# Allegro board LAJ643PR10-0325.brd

Outline 313.6 x 137.82 mm; copper layers: TOP, GND1, IN1, VCC, IN2, IN3, GND2, BOTTOM. Coordinates in mm from the lower left corner of the outline.

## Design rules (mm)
net group CLK_CNV_PRX_DTX_: nets CLK_CNV_PRX_DTX_N CLK_CNV_PRX_DTX_P
net group CLK_CNV_PTX_DRX_: nets CLK_CNV_PTX_DRX_N CLK_CNV_PTX_DRX_P
net group CNV_PRX_DTX_0: nets CNV_PRX_DTX_N0 CNV_PRX_DTX_P0
net group CNV_PRX_DTX_1: nets CNV_PRX_DTX_N1 CNV_PRX_DTX_P1
net group CNV_PTX_DRX_0: nets CNV_PTX_DRX_N0 CNV_PTX_DRX_P0
net group CNV_PTX_DRX_1: nets CNV_PTX_DRX_N1 CNV_PTX_DRX_P1
net group DDR_ALERT: nets DDR_M0_ALERT# DDR_M1_ALERT#
net group DDR_M0_CLK0: nets DDR_M0_CLK0 DDR_M0_CLK#0
net group DDR_M0_CLK1: nets DDR_M0_CLK1 DDR_M0_CLK#1
net group DDR_M0_DQS0: nets DDR_M0_DQS0 DDR_M0_DQS#0
net group DDR_M0_DQS1: nets DDR_M0_DQS1 DDR_M0_DQS#1
net group DDR_M0_DQS2: nets DDR_M0_DQS2 DDR_M0_DQS#2
net group DDR_M0_DQS3: nets DDR_M0_DQS3 DDR_M0_DQS#3
net group DDR_M0_DQS4: nets DDR_M0_DQS4 DDR_M0_DQS#4
net group DDR_M0_DQS5: nets DDR_M0_DQS5 DDR_M0_DQS#5
net group DDR_M0_DQS6: nets DDR_M0_DQS6 DDR_M0_DQS#6
net group DDR_M0_DQS7: nets DDR_M0_DQS7 DDR_M0_DQS#7
net group DDR_M1_CLK0: nets DDR_M1_CLK0 DDR_M1_CLK#0
net group DDR_M1_CLK1: nets DDR_M1_CLK1 DDR_M1_CLK#1
net group DDR_M1_DQS0: nets DDR_M1_DQS0 DDR_M1_DQS#0
net group DDR_M1_DQS1: nets DDR_M1_DQS1 DDR_M1_DQS#1
net group DDR_M1_DQS2: nets DDR_M1_DQS2 DDR_M1_DQS#2
net group DDR_M1_DQS3: nets DDR_M1_DQS3 DDR_M1_DQS#3
net group DDR_M1_DQS4: nets DDR_M1_DQS4 DDR_M1_DQS#4
net group DDR_M1_DQS5: nets DDR_M1_DQS5 DDR_M1_DQS#5
net group DDR_M1_DQS6: nets DDR_M1_DQS6 DDR_M1_DQS#6
net group DDR_M1_DQS7: nets DDR_M1_DQS7 DDR_M1_DQS#7
net group DMI_CRX_PTX_0: nets DMI_CRX_PTX_N0 DMI_CRX_PTX_P0
net group DMI_CRX_PTX_1: nets DMI_CRX_PTX_N1 DMI_CRX_PTX_P1
net group DMI_CRX_PTX_2: nets DMI_CRX_PTX_N2 DMI_CRX_PTX_P2
net group DMI_CRX_PTX_3: nets DMI_CRX_PTX_N3 DMI_CRX_PTX_P3
net group DMI_CTX_PRX_0: nets DMI_CTX_PRX_N0 DMI_CTX_PRX_P0
net group DMI_CTX_PRX_1: nets DMI_CTX_PRX_N1 DMI_CTX_PRX_P1
net group DMI_CTX_PRX_2: nets DMI_CTX_PRX_N2 DMI_CTX_PRX_P2
net group DMI_CTX_PRX_3: nets DMI_CTX_PRX_N3 DMI_CTX_PRX_P3
net group EDP_AUX: nets EDP_AUXN EDP_AUXP
net group EDP_AUX_C: nets EDP_AUXN_C EDP_AUXP_C
net group EDP_TX0: nets EDP_TXN0 EDP_TXP0
net group EDP_TX0_C: nets EDP_TXN0_C EDP_TXP0_C
net group EDP_TX1: nets EDP_TXN1 EDP_TXP1
net group EDP_TX1_C: nets EDP_TXN1_C EDP_TXP1_C
net group EDP_TX2: nets EDP_TXN2 EDP_TXP2
net group EDP_TX2_C: nets EDP_TXN2_C EDP_TXP2_C
net group EDP_TX3: nets EDP_TXN3 EDP_TXP3
net group EDP_TX3_C: nets EDP_TXN3_C EDP_TXP3_C
net group FBA_CLKA0: nets FBA_CLKA0 FBA_CLKA0#
net group FBA_CLKA1: nets FBA_CLKA1 FBA_CLKA1#
net group FBA_WCK01: nets FBA_WCK01 FBA_WCK01#
net group FBA_WCK23: nets FBA_WCK23 FBA_WCK23#
net group FBA_WCK45: nets FBA_WCK45 FBA_WCK45#
net group FBA_WCK67: nets FBA_WCK67 FBA_WCK67#
net group FBB_CLKA0: nets FBB_CLKA0 FBB_CLKA0#
net group FBB_CLKA1: nets FBB_CLKA1 FBB_CLKA1#
net group FBB_WCK01: nets FBB_WCK01 FBB_WCK01#
net group FBB_WCK23: nets FBB_WCK23 FBB_WCK23#
net group FBB_WCK45: nets FBB_WCK45 FBB_WCK45#
net group FBB_WCK67: nets FBB_WCK67 FBB_WCK67#
net group GPU_DPE_0: nets GPU_DPE_N0 GPU_DPE_P0
net group GPU_DPE_0_C: nets GPU_DPE_N0_C GPU_DPE_P0_C
net group GPU_DPE_1: nets GPU_DPE_N1 GPU_DPE_P1
net group GPU_DPE_1_C: nets GPU_DPE_N1_C GPU_DPE_P1_C
net group GPU_DPE_2: nets GPU_DPE_N2 GPU_DPE_P2
net group GPU_DPE_2_C: nets GPU_DPE_N2_C GPU_DPE_P2_C
net group GPU_DPE_3: nets GPU_DPE_N3 GPU_DPE_P3
net group GPU_DPE_3_C: nets GPU_DPE_N3_C GPU_DPE_P3_C
net group GPU_DPE_AUX: nets GPU_DPE_AUXN GPU_DPE_AUXP
net group GPU_DPE_AUX_C: nets GPU_DPE_AUXN_C GPU_DPE_AUXP_C
net group GPU_HDMI_TX0: nets GPU_HDMI_TX0N GPU_HDMI_TX0P
net group GPU_HDMI_TX0_C: nets GPU_HDMI_TX0N_C GPU_HDMI_TX0P_C
net group GPU_HDMI_TX1: nets GPU_HDMI_TX1N GPU_HDMI_TX1P
net group GPU_HDMI_TX1_C: nets GPU_HDMI_TX1N_C GPU_HDMI_TX1P_C
net group GPU_HDMI_TX2: nets GPU_HDMI_TX2N GPU_HDMI_TX2P
net group GPU_HDMI_TX2_C: nets GPU_HDMI_TX2N_C GPU_HDMI_TX2P_C
net group GPU_HDMI_TXC: nets GPU_HDMI_TXCN GPU_HDMI_TXCP
net group GPU_HDMI_TXC_C: nets GPU_HDMI_TXCN_C GPU_HDMI_TXCP_C
net group LAN_MDI0: nets LAN_MDIN0 LAN_MDIP0
net group LAN_MDI1: nets LAN_MDIN1 LAN_MDIP1
net group LAN_MDI2: nets LAN_MDIN2 LAN_MDIP2
net group LAN_MDI3: nets LAN_MDIN3 LAN_MDIP3
net group LPC_CLK: nets CLK_PCI_LPC CLKOUT_LPC0
net group PCIE_PRX_DTX_9: nets PCIE_PRX_DTX_N9 PCIE_PRX_DTX_P9
net group PCIE_PRX_DTX_10: nets PCIE_PRX_DTX_N10 PCIE_PRX_DTX_P10
net group PCIE_PRX_DTX_11: nets PCIE_PRX_DTX_N11 PCIE_PRX_DTX_P11
net group PCIE_PRX_DTX_12: nets PCIE_PRX_DTX_N12 PCIE_PRX_DTX_P12
net group PCIE_PTX_C_DRX_9: nets PCIE_PTX_C_DRX_N9 PCIE_PTX_C_DRX_P9
net group PCIE_PTX_C_DRX_10: nets PCIE_PTX_C_DRX_N10 PCIE_PTX_C_DRX_P10
net group PCIE_PTX_C_DRX_11: nets PCIE_PTX_C_DRX_N11 PCIE_PTX_C_DRX_P11
net group PCIE_PTX_C_DRX_12: nets PCIE_PTX_C_DRX_N12 PCIE_PTX_C_DRX_P12
net group PCIE_PTX_DRX_9: nets PCIE_PTX_DRX_N9 PCIE_PTX_DRX_P9
net group PCIE_PTX_DRX_10: nets PCIE_PTX_DRX_N10 PCIE_PTX_DRX_P10
net group PCIE_PTX_DRX_11: nets PCIE_PTX_DRX_N11 PCIE_PTX_DRX_P11
net group PCIE_PTX_DRX_12: nets PCIE_PTX_DRX_N12 PCIE_PTX_DRX_P12
net group PCIE_RCOMP: nets PCIE_RCOMPN PCIE_RCOMPP
net group PEG_CRX_C_GTX_0: nets PEG_CRX_C_GTX_N0 PEG_CRX_C_GTX_P0
net group PEG_CRX_C_GTX_1: nets PEG_CRX_C_GTX_N1 PEG_CRX_C_GTX_P1
net group PEG_CRX_C_GTX_2: nets PEG_CRX_C_GTX_N2 PEG_CRX_C_GTX_P2
net group PEG_CRX_C_GTX_3: nets PEG_CRX_C_GTX_N3 PEG_CRX_C_GTX_P3
net group PEG_CRX_C_GTX_4: nets PEG_CRX_C_GTX_N4 PEG_CRX_C_GTX_P4
net group PEG_CRX_C_GTX_5: nets PEG_CRX_C_GTX_N5 PEG_CRX_C_GTX_P5
net group PEG_CRX_C_GTX_6: nets PEG_CRX_C_GTX_N6 PEG_CRX_C_GTX_P6
net group PEG_CRX_C_GTX_7: nets PEG_CRX_C_GTX_N7 PEG_CRX_C_GTX_P7
net group PEG_CRX_GTX_0: nets PEG_CRX_GTX_N0 PEG_CRX_GTX_P0
net group PEG_CRX_GTX_1: nets PEG_CRX_GTX_N1 PEG_CRX_GTX_P1
net group PEG_CRX_GTX_2: nets PEG_CRX_GTX_N2 PEG_CRX_GTX_P2
net group PEG_CRX_GTX_3: nets PEG_CRX_GTX_N3 PEG_CRX_GTX_P3
net group PEG_CRX_GTX_4: nets PEG_CRX_GTX_N4 PEG_CRX_GTX_P4
net group PEG_CRX_GTX_5: nets PEG_CRX_GTX_N5 PEG_CRX_GTX_P5
net group PEG_CRX_GTX_6: nets PEG_CRX_GTX_N6 PEG_CRX_GTX_P6
net group PEG_CRX_GTX_7: nets PEG_CRX_GTX_N7 PEG_CRX_GTX_P7
net group PEG_CTX_C_GRX_0: nets PEG_CTX_C_GRX_N0 PEG_CTX_C_GRX_P0
net group PEG_CTX_C_GRX_1: nets PEG_CTX_C_GRX_N1 PEG_CTX_C_GRX_P1
net group PEG_CTX_C_GRX_2: nets PEG_CTX_C_GRX_N2 PEG_CTX_C_GRX_P2
net group PEG_CTX_C_GRX_3: nets PEG_CTX_C_GRX_N3 PEG_CTX_C_GRX_P3
net group PEG_CTX_C_GRX_4: nets PEG_CTX_C_GRX_N4 PEG_CTX_C_GRX_P4
net group PEG_CTX_C_GRX_5: nets PEG_CTX_C_GRX_N5 PEG_CTX_C_GRX_P5
net group PEG_CTX_C_GRX_6: nets PEG_CTX_C_GRX_N6 PEG_CTX_C_GRX_P6
net group PEG_CTX_C_GRX_7: nets PEG_CTX_C_GRX_N7 PEG_CTX_C_GRX_P7
net group PEG_CTX_GRX_0: nets PEG_CTX_GRX_N0 PEG_CTX_GRX_P0
net group PEG_CTX_GRX_1: nets PEG_CTX_GRX_N1 PEG_CTX_GRX_P1
net group PEG_CTX_GRX_2: nets PEG_CTX_GRX_N2 PEG_CTX_GRX_P2
net group PEG_CTX_GRX_3: nets PEG_CTX_GRX_N3 PEG_CTX_GRX_P3
net group PEG_CTX_GRX_4: nets PEG_CTX_GRX_N4 PEG_CTX_GRX_P4
net group PEG_CTX_GRX_5: nets PEG_CTX_GRX_N5 PEG_CTX_GRX_P5
net group PEG_CTX_GRX_6: nets PEG_CTX_GRX_N6 PEG_CTX_GRX_P6
net group PEG_CTX_GRX_7: nets PEG_CTX_GRX_N7 PEG_CTX_GRX_P7
net group QPC: nets QPCN QPCP
net group RJ45_RX1: nets RJ45_RX1+ RJ45_RX1-
net group RJ45_TX0: nets RJ45_TX0+ RJ45_TX0-
net group RJ45_TX2: nets RJ45_TX2+ RJ45_TX2-
net group RJ45_TX3: nets RJ45_TX3+ RJ45_TX3-
net group SPK_L_CONN: nets SPK_L+_CONN SPK_L-_CONN
net group SPK_OUT_L: nets SPK_OUT_L+ SPK_OUT_L-
net group SPK_OUT_R: nets SPK_OUT_R+ SPK_OUT_R-
net group SPK_R_CONN: nets SPK_R+_CONN SPK_R-_CONN
net group SR_R: nets SRN_R SRP_R
net group TMDS_SNK_ML0_: nets TMDS_SNK_ML0_N TMDS_SNK_ML0_P
net group TMDS_SNK_ML0__R: nets TMDS_SNK_ML0_N_R TMDS_SNK_ML0_P_R
net group TMDS_SNK_ML1_: nets TMDS_SNK_ML1_N TMDS_SNK_ML1_P
net group TMDS_SNK_ML1__R: nets TMDS_SNK_ML1_N_R TMDS_SNK_ML1_P_R
net group TMDS_SNK_ML2_: nets TMDS_SNK_ML2_N TMDS_SNK_ML2_P
net group TMDS_SNK_ML2__R: nets TMDS_SNK_ML2_N_R TMDS_SNK_ML2_P_R
net group TMDS_SNK_ML3_: nets TMDS_SNK_ML3_N TMDS_SNK_ML3_P
net group TMDS_SNK_ML3__R: nets TMDS_SNK_ML3_N_R TMDS_SNK_ML3_P_R
net group U2D_D1: nets U2D_DN1 U2D_DP1
net group USB3_DPE_MRX_C_DTX_1: nets USB3_DPE_MRX_C_DTX_N1 USB3_DPE_MRX_C_DTX_P1
net group USB3_DPE_MRX_C_DTX_2: nets USB3_DPE_MRX_C_DTX_N2 USB3_DPE_MRX_C_DTX_P2
net group USB3_DPE_MRX_DTX_1: nets USB3_DPE_MRX_DTX_N1 USB3_DPE_MRX_DTX_P1
net group USB3_DPE_MRX_DTX_2: nets USB3_DPE_MRX_DTX_N2 USB3_DPE_MRX_DTX_P2
net group USB3_DPE_MTX_C_DRX_1: nets USB3_DPE_MTX_C_DRX_N1 USB3_DPE_MTX_C_DRX_P1
net group USB3_DPE_MTX_C_DRX_2: nets USB3_DPE_MTX_C_DRX_N2 USB3_DPE_MTX_C_DRX_P2
net group USB3_DPE_MTX_DRX_1: nets USB3_DPE_MTX_DRX_N1 USB3_DPE_MTX_DRX_P1
net group USB3_DPE_MTX_DRX_2: nets USB3_DPE_MTX_DRX_N2 USB3_DPE_MTX_DRX_P2
net group USB3_PRX_C_MTX_4: nets USB3_PRX_C_MTX_N4 USB3_PRX_C_MTX_P4
net group USB3_PRX_DTX_1: nets USB3_PRX_DTX_N1 USB3_PRX_DTX_P1
net group USB3_PRX_DTX_2: nets USB3_PRX_DTX_N2 USB3_PRX_DTX_P2
net group USB3_PRX_DTX_3: nets USB3_PRX_DTX_N3 USB3_PRX_DTX_P3
net group USB3_PRX_MTX_4: nets USB3_PRX_MTX_N4 USB3_PRX_MTX_P4
net group USB3_PRX_R_DTX_1: nets USB3_PRX_R_DTX_N1 USB3_PRX_R_DTX_P1
net group USB3_PTX_C_DRX_1: nets USB3_PTX_C_DRX_N1 USB3_PTX_C_DRX_P1
net group USB3_PTX_C_MRX_4: nets USB3_PTX_C_MRX_N4 USB3_PTX_C_MRX_P4
net group USB3_PTX_DRX_1: nets USB3_PTX_DRX_N1 USB3_PTX_DRX_P1
net group USB3_PTX_DRX_2: nets USB3_PTX_DRX_N2 USB3_PTX_DRX_P2
net group USB3_PTX_DRX_3: nets USB3_PTX_DRX_N3 USB3_PTX_DRX_P3
net group USB3_PTX_MRX_4: nets USB3_PTX_MRX_N4 USB3_PTX_MRX_P4
net group USB3_PTX_R_DRX_1: nets USB3_PTX_R_DRX_N1 USB3_PTX_R_DRX_P1
net group USB20_1: nets USB20_N1 USB20_P1
net group USB20_1_C: nets USB20_N1_C USB20_P1_C
net group USB20_2: nets USB20_N2 USB20_P2
net group USB20_3: nets USB20_N3 USB20_P3
net group USB20_4: nets USB20_N4 USB20_P4
net group USB20_4_L: nets USB20_N4_L USB20_P4_L
net group USB20_5: nets USB20_N5 USB20_P5
net group USB20_5_R: nets USB20_N5_R USB20_P5_R
net group USB20_6: nets USB20_N6 USB20_P6
net group USB20_9: nets USB20_N9 USB20_P9
net group USB20_14: nets USB20_N14 USB20_P14
net group W12: nets +PD_CC1 +PD_CC2
net group W15: nets DP_RCOMP PEG_RCOMP
net group COMBO JACK: nets +MIC2_VREFO HP_OUT_L HP_OUT_R HP_OUTL HP_OUTR HPOUT_L HPOUT_R INT_MIC INT_MIC_R
net group CPU_SIDEBAND: nets CPU_TRIGOUT CPU_TRIGOUT_R DDR_DRAMRST#_R DRAM_RESET# EC_PECI EC_VCCST_PG EC_VCCST_PG_R H_CPUPWRGD H_PECI H_PLTRST_CPU# H_PM_DOWN H_PM_DOWN_R H_PM_SYNC H_PM_SYNC_R H_PROCHOT# H_PROCHOT#_EC H_THERMTRIP# PCH_THERMTRIP# PCH_THERMTRIP#_R PCH_TRIGOUT PCH_TRIGOUT_R VR_HOT#
net group DDR_M0_CMD: nets DDR_M0_ACT# DDR_M0_BA0 DDR_M0_BA1 DDR_M0_BG0 DDR_M0_BG1 DDR_M0_MA0 DDR_M0_MA1 DDR_M0_MA2 DDR_M0_MA3 DDR_M0_MA4 DDR_M0_MA5 DDR_M0_MA6 DDR_M0_MA7 DDR_M0_MA8 DDR_M0_MA9 DDR_M0_MA10 DDR_M0_MA11 DDR_M0_MA12 DDR_M0_MA13 DDR_M0_MA14_WE# DDR_M0_MA15_CAS# DDR_M0_MA16_RAS# DDR_M0_PAR
net group DDR_M0_CTRL: nets DDR_M0_CKE0 DDR_M0_CKE1 DDR_M0_CS#0 DDR_M0_CS#1 DDR_M0_ODT0 DDR_M0_ODT1
net group DDR_M0_D0: nets DDR_M0_D0 DDR_M0_D1 DDR_M0_D2 DDR_M0_D3 DDR_M0_D4 DDR_M0_D5 DDR_M0_D6 DDR_M0_D7
net group DDR_M0_D1: nets DDR_M0_D8 DDR_M0_D9 DDR_M0_D10 DDR_M0_D11 DDR_M0_D12 DDR_M0_D13 DDR_M0_D14 DDR_M0_D15
net group DDR_M0_D2: nets DDR_M0_D16 DDR_M0_D17 DDR_M0_D18 DDR_M0_D19 DDR_M0_D20 DDR_M0_D21 DDR_M0_D22 DDR_M0_D23
net group DDR_M0_D3: nets DDR_M0_D24 DDR_M0_D25 DDR_M0_D26 DDR_M0_D27 DDR_M0_D28 DDR_M0_D29 DDR_M0_D30 DDR_M0_D31
net group DDR_M0_D4: nets DDR_M0_D32 DDR_M0_D33 DDR_M0_D34 DDR_M0_D35 DDR_M0_D36 DDR_M0_D37 DDR_M0_D38 DDR_M0_D39
net group DDR_M0_D5: nets DDR_M0_D40 DDR_M0_D41 DDR_M0_D42 DDR_M0_D43 DDR_M0_D44 DDR_M0_D45 DDR_M0_D46 DDR_M0_D47
net group DDR_M0_D6: nets DDR_M0_D48 DDR_M0_D49 DDR_M0_D50 DDR_M0_D51 DDR_M0_D52 DDR_M0_D53 DDR_M0_D54 DDR_M0_D55
net group DDR_M0_D7: nets DDR_M0_D56 DDR_M0_D57 DDR_M0_D58 DDR_M0_D59 DDR_M0_D60 DDR_M0_D61 DDR_M0_D62 DDR_M0_D63
net group DDR_M1_CMD: nets DDR_M1_ACT# DDR_M1_BA0 DDR_M1_BA1 DDR_M1_BG0 DDR_M1_BG1 DDR_M1_MA0 DDR_M1_MA1 DDR_M1_MA2 DDR_M1_MA3 DDR_M1_MA4 DDR_M1_MA5 DDR_M1_MA6 DDR_M1_MA7 DDR_M1_MA8 DDR_M1_MA9 DDR_M1_MA10 DDR_M1_MA11 DDR_M1_MA12 DDR_M1_MA13 DDR_M1_MA14_WE# DDR_M1_MA15_CAS# DDR_M1_MA16_RAS# DDR_M1_PAR
net group DDR_M1_CTRL: nets DDR_M1_CKE0 DDR_M1_CKE1 DDR_M1_CS#0 DDR_M1_CS#1 DDR_M1_ODT0 DDR_M1_ODT1
net group DDR_M1_D0: nets DDR_M1_D0 DDR_M1_D1 DDR_M1_D2 DDR_M1_D3 DDR_M1_D4 DDR_M1_D5 DDR_M1_D6 DDR_M1_D7
net group DDR_M1_D1: nets DDR_M1_D8 DDR_M1_D9 DDR_M1_D10 DDR_M1_D11 DDR_M1_D12 DDR_M1_D13 DDR_M1_D14 DDR_M1_D15
net group DDR_M1_D2: nets DDR_M1_D16 DDR_M1_D17 DDR_M1_D18 DDR_M1_D19 DDR_M1_D20 DDR_M1_D21 DDR_M1_D22 DDR_M1_D23
net group DDR_M1_D3: nets DDR_M1_D24 DDR_M1_D25 DDR_M1_D26 DDR_M1_D27 DDR_M1_D28 DDR_M1_D29 DDR_M1_D30 DDR_M1_D31
net group DDR_M1_D4: nets DDR_M1_D32 DDR_M1_D33 DDR_M1_D34 DDR_M1_D35 DDR_M1_D36 DDR_M1_D37 DDR_M1_D38 DDR_M1_D39
net group DDR_M1_D5: nets DDR_M1_D40 DDR_M1_D41 DDR_M1_D42 DDR_M1_D43 DDR_M1_D44 DDR_M1_D45 DDR_M1_D46 DDR_M1_D47
net group DDR_M1_D6: nets DDR_M1_D48 DDR_M1_D49 DDR_M1_D50 DDR_M1_D51 DDR_M1_D52 DDR_M1_D53 DDR_M1_D54 DDR_M1_D55
net group DDR_M1_D7: nets DDR_M1_D56 DDR_M1_D57 DDR_M1_D58 DDR_M1_D59 DDR_M1_D60 DDR_M1_D61 DDR_M1_D62 DDR_M1_D63
net group FBA_CMD: nets FBA_CMD0 FBA_CMD1 FBA_CMD2 FBA_CMD3 FBA_CMD4 FBA_CMD5 FBA_CMD6 FBA_CMD7 FBA_CMD8 FBA_CMD9 FBA_CMD10 FBA_CMD11 FBA_CMD12 FBA_CMD13 FBA_CMD14 FBA_CMD15 FBA_CMD16 FBA_CMD17 FBA_CMD18 FBA_CMD19 FBA_CMD20 FBA_CMD21 FBA_CMD22 FBA_CMD23 FBA_CMD24 FBA_CMD25 FBA_CMD26 FBA_CMD27 FBA_CMD28 FBA_CMD29 FBA_CMD30 FBA_CMD31
net group FBA_D0: nets FBA_D0 FBA_D1 FBA_D2 FBA_D3 FBA_D4 FBA_D5 FBA_D6 FBA_D7
net group FBA_D1: nets FBA_D8 FBA_D9 FBA_D10 FBA_D11 FBA_D12 FBA_D13 FBA_D14 FBA_D15
net group FBA_D2: nets FBA_D16 FBA_D17 FBA_D18 FBA_D19 FBA_D20 FBA_D21 FBA_D22 FBA_D23
net group FBA_D3: nets FBA_D24 FBA_D25 FBA_D26 FBA_D27 FBA_D28 FBA_D29 FBA_D30 FBA_D31
net group FBA_D4: nets FBA_D32 FBA_D33 FBA_D34 FBA_D35 FBA_D36 FBA_D37 FBA_D38 FBA_D39
net group FBA_D5: nets FBA_D40 FBA_D41 FBA_D42 FBA_D43 FBA_D44 FBA_D45 FBA_D46 FBA_D47
net group FBA_D6: nets FBA_D48 FBA_D49 FBA_D50 FBA_D51 FBA_D52 FBA_D53 FBA_D54 FBA_D55
net group FBA_D7: nets FBA_D56 FBA_D57 FBA_D58 FBA_D59 FBA_D60 FBA_D61 FBA_D62 FBA_D63
net group FBA_DBI: nets FBA_DBI0 FBA_DBI1 FBA_DBI2 FBA_DBI3 FBA_DBI4 FBA_DBI5 FBA_DBI6 FBA_DBI7
net group FBA_EDC: nets FBA_EDC0 FBA_EDC1 FBA_EDC2 FBA_EDC3 FBA_EDC4 FBA_EDC5 FBA_EDC6 FBA_EDC7
net group FBB_CMD: nets FBB_CMD0 FBB_CMD1 FBB_CMD2 FBB_CMD3 FBB_CMD4 FBB_CMD5 FBB_CMD6 FBB_CMD7 FBB_CMD8 FBB_CMD9 FBB_CMD10 FBB_CMD11 FBB_CMD12 FBB_CMD13 FBB_CMD14 FBB_CMD15 FBB_CMD16 FBB_CMD17 FBB_CMD18 FBB_CMD19 FBB_CMD20 FBB_CMD21 FBB_CMD22 FBB_CMD23 FBB_CMD24 FBB_CMD25 FBB_CMD26 FBB_CMD27 FBB_CMD28 FBB_CMD29 FBB_CMD30 FBB_CMD31
net group FBB_D0: nets FBB_D0 FBB_D1 FBB_D2 FBB_D3 FBB_D4 FBB_D5 FBB_D6 FBB_D7
net group FBB_D1: nets FBB_D8 FBB_D9 FBB_D10 FBB_D11 FBB_D12 FBB_D13 FBB_D14 FBB_D15
net group FBB_D2: nets FBB_D16 FBB_D17 FBB_D18 FBB_D19 FBB_D20 FBB_D21 FBB_D22 FBB_D23
net group FBB_D3: nets FBB_D24 FBB_D25 FBB_D26 FBB_D27 FBB_D28 FBB_D29 FBB_D30 FBB_D31
net group FBB_D4: nets FBB_D32 FBB_D33 FBB_D34 FBB_D35 FBB_D36 FBB_D37 FBB_D38 FBB_D39
net group FBB_D5: nets FBB_D40 FBB_D41 FBB_D42 FBB_D43 FBB_D44 FBB_D45 FBB_D46 FBB_D47
net group FBB_D6: nets FBB_D48 FBB_D49 FBB_D50 FBB_D51 FBB_D52 FBB_D53 FBB_D54 FBB_D55
net group FBB_D7: nets FBB_D56 FBB_D57 FBB_D58 FBB_D59 FBB_D60 FBB_D61 FBB_D62 FBB_D63
net group FBB_DBI: nets FBB_DBI0 FBB_DBI1 FBB_DBI2 FBB_DBI3 FBB_DBI4 FBB_DBI5 FBB_DBI6 FBB_DBI7
net group FBB_EDC: nets FBB_EDC0 FBB_EDC1 FBB_EDC2 FBB_EDC3 FBB_EDC4 FBB_EDC5 FBB_EDC6 FBB_EDC7
net group I2C: nets I2C_0_SCL I2C_0_SDA I2C_1_SCL I2C_1_SDA
net group LPC_DATA: nets LPC_AD0 LPC_AD1 LPC_AD2 LPC_AD3 LPC_FRAME# SERIRQ
net group PCIE: nets PCIE_PRX_C_DTX_N14 PCIE_PRX_C_DTX_N15 PCIE_PRX_C_DTX_P14 PCIE_PRX_C_DTX_P15 PCIE_PRX_DTX_N14 PCIE_PRX_DTX_N15 PCIE_PRX_DTX_N16 PCIE_PRX_DTX_P14 PCIE_PRX_DTX_P15 PCIE_PRX_DTX_P16 PCIE_PTX_C_DRX_N14 PCIE_PTX_C_DRX_N15 PCIE_PTX_C_DRX_N16 PCIE_PTX_C_DRX_P14 PCIE_PTX_C_DRX_P15 PCIE_PTX_C_DRX_P16 PCIE_PTX_DRX_N14 PCIE_PTX_DRX_N15 PCIE_PTX_DRX_N16 PCIE_PTX_DRX_P14 PCIE_PTX_DRX_P15 PCIE_PTX_DRX_P16
net group PLATFORM CLK_S: nets PCH_RTCX1 PCH_RTCX2 XTAL_24M_PCH_IN XTAL_24M_PCH_IN_R XTAL_24M_PCH_OUT XTAL_24M_PCH_OUT_R XTALIN XTALOUT XTALOUT_R XTLI XTLO XTLO_R
net group PLATFORM_CLK: nets CLK_PCIE_N1 CLK_PCIE_N2 CLK_PCIE_N3 CLK_PCIE_N5 CLK_PCIE_P1 CLK_PCIE_P2 CLK_PCIE_P3 CLK_PCIE_P5 CLK_PEG_N4 CLK_PEG_P4 PCH_CPU_24M_CLK_N PCH_CPU_24M_CLK_P PCH_CPU_BCLK_N PCH_CPU_BCLK_P PCH_CPU_PCIBCLK_N PCH_CPU_PCIBCLK_P PCH_XDP_CLK_R_DN PCH_XDP_CLK_R_DP
net group POWER: nets +0.6V_B_VREFDQ +0.6V_VREFCA +0.6VS_VTT +1.0VSDGPU +1.05V_VCCDSW +1.05V_VCCUSB +1.8V_PHVLDO +1.8V_PRIM +1.8VS_AVDD +1.35VSDGPU +3V_1.8V_PGPPHK +5V_HDMI +5V_TYPEC_L +5VS_AVDD +5VS_KBL +5VS_PVDD +DVDD +FB_PLLAVDD +GPU_PLLVDD +LAN_VDD_1V0 +LAN_VDD_3V3 +LCDVDD +USB_VCC2 FBA0_VREFC FBA1_VREFC FBB0_VREFC FBB1_VREFC INVPWR_B+
net group RST: nets DGPU_HOLD_RST# EC_KBRST# PCH_PLTRST# PCH_RSMRST# PCH_RTCRST# PLT_RST# PLT_RST#_R PLT_RST#_TPM SYS_RESET#
net group S-8: nets HDA_RST# HDA_RST#_R HDA_SDOUT HDA_SDOUT_R HDA_SYNC HDA_SYNC_R N17435076
net group S-12: nets CNV_WT_RCOMP
net group S-15: nets HDA_BIT_CLK HDA_BIT_CLK_R USB2_RCOMP
net group S-25: nets SM_RCOMP0 SM_RCOMP1 SM_RCOMP2
net group SATA: nets SATA_PRX_C_DTX_N0 SATA_PRX_C_DTX_P0 SATA_PRX_DTX_N0 SATA_PRX_DTX_P0 SATA_PTX_C_DRX_N0 SATA_PTX_C_DRX_P0 SATA_PTX_DRX_N0 SATA_PTX_DRX_P0
net group SD: nets SD_CD# SD_CLK SD_CLK_R SD_CMD SD_CMD_R SD_D0 SD_D0_R SD_D1 SD_D1_R SD_D2 SD_D2_R SD_D3 SD_D3_R SD_WP
net group SENSE: nets VCCGT_SENSE VCCSA_SENSE VCCSENSE VSSGT_SENSE VSSSA_SENSE VSSSENSE
net group SMBUS: nets EC_SMB_CK2 EC_SMB_CK2_PD EC_SMB_DA2 EC_SMB_DA2_PD PCH_SMBCLK PCH_SMBDATA PCH_SML1CLK PCH_SML1DATA SMBUS_CLK SMBUS_DAT TP_SMBCLK TP_SMBDATA VGA_I2CS_SCL VGA_I2CS_SDA
net group SPI: nets EC_MISO EC_MOSI EC_SPICLK EC_SPICLK_R EC_SPICS# PCH_CS_TPM PCH_SPI_CLK PCH_SPI_CLK_R PCH_SPI_CLK_TPM PCH_SPI_CS#0 PCH_SPI_HOLD# PCH_SPI_HOLD#_R PCH_SPI_SI PCH_SPI_SI_R PCH_SPI_SI_TPM PCH_SPI_SO PCH_SPI_SO_R PCH_SPI_SO_TPM PCH_SPI_WP# PCH_SPI_WP#_R
net group SVID: nets CPU_SVID_ALERT# CPU_SVID_ALERT#_R CPU_SVID_CLK CPU_SVID_CLK_R CPU_SVID_DAT CPU_SVID_DAT_R
net group SW: nets CHG_PHASE DH_CHG DH_CHG_R DL_CHG HGATE_1.35VSDGPUP LG_DDR LG_GT LG_PH1 LG_PH2 LG_PH3 LG_PH4 LG_VCCSA LGATE_1.35VSDGPUP LX_1.35VSDGPUP LX_DDR LX_GT LX_GT_R LX_PH1 LX_PH1_R LX_PH2 LX_PH2_R LX_PH3 LX_PH3_R LX_PH4 LX_PH4_R LX_VCCSA NVVDD_LG3 NVVDD_LX1 NVVDD_LX1_1 NVVDD_LX2 NVVDD_LX2_1 NVVDD_LX3 NVVDD_LX3_1 NVVDD_UG1 NVVDD_UG1_R NVVDD_UG2 NVVDD_UG2_R NVVDD_UG3 NVVDD_UG3_R UG_DDR UG_GT UG_PH1 UG_PH2 UG_PH3 UG_PH4 UG_VCCSA UG_VCCSA_R
net group W4: nets CFG_RCOMP
net group W20: nets +0.6VSP +1.05V_PCH +1.8VALW +1.8VALWP +1.8VS +3VALW_DSW +3VALWP +5VALWP
net group XDP: nets CFG0 CFG2 CFG4 CFG5 CFG6 CFG7 CPU_XDP_TCK0 CPU_XDP_TDI CPU_XDP_TDO CPU_XDP_TMS CPU_XDP_TRST# XDP_PRDY# XDP_PREQ#
nets with their own width: min track width 0.254; nets ECAGND VCIN1_PH
nets with their own width: min track width 0.508; nets NVVDD_SNUB2

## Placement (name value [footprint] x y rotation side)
C365  10U_0402_6.3V6M  [C_0402]  18.24 3.6 90 top
C366  0.1U_0201_10V6K  [C_0201]  18.12 2.44 180 top
C367  1U_0201_6.3V6M  [C_0201]  36.4 2.06 0 top
C368  47U_0603_6.3V6M  [C_0603]  19.21 4.52 0 top
C369  0.22U_0402_10V6K  [C_0402]  35.44 8 180 top
C370  0.22U_0402_10V6K  [C_0402]  35.44 7.11 180 top
C371  0.22U_0402_10V6K  [C_0402]  30.56 5.99 90 top
C372  0.22U_0402_10V6K  [C_0402]  29.67 5.99 90 top
C373  0.22U_0402_10V6K  [C_0402]  27.67 5.87 90 top
C374  0.22U_0402_10V6K  [C_0402]  26.7 5.87 90 top
C375  0.22U_0402_10V6K  [C_0402]  24.67 5.99 90 top
C376  0.22U_0402_10V6K  [C_0402]  23.7 5.99 90 top
C378  0.01U_0402_16V7K  [C_0402]  256.17 20.25 270 bottom
C379  0.01U_0402_16V7K  [C_0402]  255.28 20.25 270 bottom
C380  0.01U_0402_16V7K  [C_0402]  254.34 20.27 270 bottom
C381  470P_0402_50V8J  [C_0402]  256.3 14.51 90 bottom
C382  0.01U_0402_16V7K  [C_0402]  253.45 20.27 270 bottom
C388  0.1U_0402_10V6K  [C_0402]  85.26 13.33 0 top
C389  100P_0402_50V8J  [C_0402]  184.61 11.45 0 top
C390  100P_0402_50V8J  [C_0402]  198.33 7.64 90 top
C391  100P_0402_50V8J  [C_0402]  201 7.64 90 top
C393  10P_0402_50V8J  [C_0402]  205.57 131.72 180 top
C394  100P_0402_50V8J  [C_0402]  205.57 130.83 180 top
C395  0.1U_0201_10V6K  [C_0201]  206.11 136.37 180 top
C400  0.1U_0402_10V6K  [C_0402]  265.22 40.46 0 top
C401  1U_0201_6.3V6M  [C_0201]  267.47 40.64 180 top
C402  1U_0201_6.3V6M  [C_0201]  269.17 42.93 90 top
C403  1000P_0402_50V7K  [C_0402]  263.82 41.56 180 top
C404  1000P_0402_50V7K  [C_0402]  263.82 42.45 180 top
C405  1U_0201_6.3V6M  [C_0201]  267.87 45.87 180 top
C406  0.1U_0402_10V6K  [C_0402]  265.03 45.11 0 top
C407  100P_0402_50V8J  [C_0402]  177.63 28.67 270 top
C408  0.1U_0402_10V6K  [C_0402]  178.52 28.67 270 top
C409  10P_0402_50V8J  [C_0402]  34.43 2.3 90 top
C410  33P_0402_50V8J  [C_0402]  32.62 2.31 90 top
C411  10P_0402_50V8J  [C_0402]  255.41 15.4 270 bottom
C412  33P_0402_50V8J  [C_0402]  254.52 15.4 270 bottom
C5245  10U_0402_6.3V6M  [C_0402]  179.68 50.26 270 top
C5246  0.1U_0201_10V6K  [C_0201]  178.28 49.88 270 top
C5247  0.1U_0201_10V6K  [C_0201]  178.92 49.88 270 top
C5249  10U_0402_6.3V6M  [C_0402]  33.53 2.31 90 top
C5250  1U_0201_6.3V6M  [C_0201]  18.12 1.8 180 top
C5251  1U_0201_6.3V6M  [C_0201]  64.64 40.79 180 top
C5253  0.1U_0402_10V6K  [C_0402]  64.65 34.44 0 top
C5254  1U_0201_6.3V6M  [C_0201]  64.64 40.16 180 top
C5255  4.7U_0402_6.3V6M  [C_0402]  64.65 33.55 0 top
C5256  10P_0402_50V8J  [C_0402]  84.86 8.41 270 top
C5257  10P_0402_50V8J  [C_0402]  85.79 8.4 270 top
C5258  10P_0402_50V8J  [C_0402]  87.35 8.37 270 top
C5259  10P_0402_50V8J  [C_0402]  88.27 8.38 270 top
C5260  10U_0402_6.3V6M  [C_0402]  258.13 14.17 180 bottom
C5263  10U_0402_6.3V6M  [C_0402]  41.05 14.09 90 top
C5274  100P_0402_50V8J  [C_0402]  65.54 32.64 180 top
C5275  10P_0402_50V8J  [C_0402]  266.97 39.91 0 top
C5276  10P_0402_50V8J  [C_0402]  266.8 45.14 0 top
C5277  0.1U_0402_10V6K  [C_0402]  176.14 32.95 270 top
C5278  10P_0402_50V8J  [C_0402]  214.27 27.32 180 top
CA1  0.1U_0201_6.3V6K  [C_0201]  293.83 16.28 180 top
CA2  10U_0402_6.3V6M  [C_0402]  294.09 14.25 0 top
CA3  0.1U_0201_6.3V6K  [C_0201]  300.31 19.71 270 top
CA4  10U_0402_6.3V6M  [C_0402]  301.07 19.71 270 top
CA5  10U_0402_6.3V6M  [C_0402]  294.47 26.69 270 top
CA11  0.1U_0201_10V6K  [C_0201]  290.4 23.01 180 top
CA12  10U_0402_10V6M  [C_0402]  289.51 23.77 0 top
CA13  0.1U_0201_6.3V6K  [C_0201]  299.78 21.87 90 top
CA14  10U_0402_6.3V6M  [C_0402]  300.51 22.88 270 top
CA15  22P_0201_25V8  [C_0201]  299.48 16.61 0 top
CA16  4.7U_0402_6.3V6M  [C_0402]  289.51 23.77 0 bottom
CA17  10U_0402_6.3V6M  [C_0402]  300.82 23.77 180 top
CA18  10U_0402_6.3V6M  [C_0402]  302.21 20.72 180 top
CA19  2.2U_0201_6.3V6M  [C_0201]  292.44 24.03 90 bottom
CA20  0.1U_0201_6.3V6K  [C_0201]  291.8 24.03 90 bottom
CA21  0.1U_0201_6.3V6K  [C_0201]  289.04 21.12 180 top
CA22  0.1U_0201_6.3V6K  [C_0201]  290.66 18.31 270 top
CA23  2.2U_0201_6.3V6M  [C_0201]  298.28 26.31 270 top
CA24  10U_0402_6.3V6M  [C_0402]  287.86 18.06 0 top
CA25  10U_0402_6.3V6M  [C_0402]  287.86 18.95 0 top
CA26  1U_0201_6.3V6K  [C_0201]  299.42 25.8 270 top
CA27  0.1U_0201_6.3V6K  [C_0201]  287.1 26.82 0 top
CA28  0.1U_0201_6.3V6K  [C_0201]  287.1 27.46 0 top
CA29  0.1U_0201_6.3V6K  [C_0201]  292.44 26.44 270 top
CA30  0.1U_0201_6.3V6K  [C_0201]  291.93 21.74 90 bottom
CA31  0.1U_0201_6.3V6K  [C_0201]  295.61 23.26 90 bottom
CA32  0.1U_0201_6.3V6K  [C_0201]  295.07 28.2 270 top
CA36  0.1U_0201_6.3V6K  [C_0201]  302.47 26.87 90 top
CA37  0.1U_0201_6.3V6K  [C_0201]  297.89 30.72 315 top
CA38  0.1U_0201_6.3V6K  [C_0201]  302.1 24.56 180 top
CA88  0.1U_0201_10V6K  [C_0201]  298.28 16.17 90 top
CA91  0.1U_0201_6.3V6K  [C_0201]  286.97 17.8 90 top
CA92  10U_0402_6.3V6M  [C_0402]  286.09 18.44 270 top
CA93  2.2P_0201_50V8C  [C_0201]  299.48 17.88 0 top
CA94  0.1U_0201_10V6K  [C_0201]  292.56 16.28 180 top
CA95  10P_0201_25V8  [C_0201]  305.01 28.34 270 bottom
CA96  10P_0201_25V8  [C_0201]  305.01 29.61 270 bottom
CA97  100P_0201_25V8J  [C_0201]  305.01 30.38 90 bottom
CA98  1U_0201_6.3V6K  [C_0201]  300.06 25.8 270 top
CC1  0.22U_0402_16V7K  [C_0402]  173.31 94.64 0 bottom
CC2  0.22U_0402_16V7K  [C_0402]  173.31 93.75 0 bottom
CC3  0.22U_0402_16V7K  [C_0402]  176.41 92.68 0 bottom
CC4  0.22U_0402_16V7K  [C_0402]  176.41 93.57 0 bottom
CC5  0.22U_0402_16V7K  [C_0402]  173.31 92.48 0 bottom
CC6  0.22U_0402_16V7K  [C_0402]  173.31 91.59 0 bottom
CC7  0.22U_0402_16V7K  [C_0402]  176.41 90.52 0 bottom
CC8  0.22U_0402_16V7K  [C_0402]  176.41 91.41 0 bottom
CC9  0.22U_0402_16V7K  [C_0402]  173.31 90.32 0 bottom
CC10  0.22U_0402_16V7K  [C_0402]  173.31 89.43 0 bottom
CC11  0.22U_0402_16V7K  [C_0402]  176.41 88.36 0 bottom
CC12  0.22U_0402_16V7K  [C_0402]  176.41 89.25 0 bottom
CC13  0.22U_0402_16V7K  [C_0402]  173.31 88.16 0 bottom
CC14  0.22U_0402_16V7K  [C_0402]  173.31 87.27 0 bottom
CC15  0.22U_0402_16V7K  [C_0402]  176.41 86.21 0 bottom
CC16  0.22U_0402_16V7K  [C_0402]  176.41 87.09 0 bottom
CC17  10U_0402_6.3V6M  [C_0402]  162.51 84.79 0 top
CC18  10U_0402_6.3V6M  [C_0402]  142.88 86.76 0 top
CC19  10U_0402_6.3V6M  [C_0402]  145.64 89.42 270 top
CC20  10U_0402_6.3V6M  [C_0402]  155.15 90.03 180 top
CC24  10U_0402_6.3V6M  [C_0402]  162.3 90.31 0 top
CC25  10U_0402_6.3V6M  [C_0402]  142.78 85.76 270 top
CC26  10U_0402_6.3V6M  [C_0402]  157.69 86.89 270 top
CC27  10U_0402_6.3V6M  [C_0402]  157.8 85.06 0 top
CC28  10U_0402_6.3V6M  [C_0402]  155.28 85.63 270 top
CC29  22U_0603_6.3V6M  [C_0603]  139.49 75.65 180 top
CC30  22U_0603_6.3V6M  [C_0603]  153.18 85.24 180 top
CC31  22U_0603_6.3V6M  [C_0603]  138.22 85.3 90 top
CC32  22U_0603_6.3V6M  [C_0603]  148.61 84.99 180 top
CC33  10U_0402_6.3V6M  [C_0402]  162.82 92.86 0 top
CC34  10U_0402_6.3V6M  [C_0402]  162.63 97.43 0 top
CC35  10U_0402_6.3V6M  [C_0402]  162.8 94.38 0 top
CC36  1U_0201_6.3V6M  [C_0201]  163.55 88.16 180 top
CC37  1U_0201_6.3V6M  [C_0201]  131.62 90.71 0 top
CC38  1U_0201_6.3V6M  [C_0201]  163.91 106.2 180 top
CC39  1U_0201_6.3V6M  [C_0201]  162.34 102.91 90 top
CC40  1U_0201_6.3V6M  [C_0201]  165.71 104.52 90 top
CC41  0.1U_0402_10V6K  [C_0402]  120.55 85.37 180 bottom
CC144  22P_0402_50V8J  [C_0402]  132.38 9.22 270 top
CC152  10U_0402_6.3V6M  [C_0402]  151.08 89.3 270 top
CC153  10U_0402_6.3V6M  [C_0402]  150.07 85.24 90 top
CC154  10U_0402_6.3V6M  [C_0402]  164.33 86.52 90 top
CC155  10P_0402_50V8J  [C_0402]  123.53 108.48 180 bottom
CC156  100P_0402_50V8J  [C_0402]  176.89 83.8 90 bottom
CC157  100P_0402_50V8J  [C_0402]  122.64 104.29 0 bottom
CC389  1U_0201_6.3V6M  [C_0201]  254.39 36.93 270 top
CC390  1U_0201_6.3V6M  [C_0201]  252.06 38.39 90 top
CC391  0.1U_0402_25V6  [C_0402]  251.96 41.15 270 top
CC392  10P_0402_50V8J  [C_0402]  253.8 42.24 90 top
CC393  1000P_0402_50V7K  [C_0402]  254.69 42.24 90 top
CC394  1U_0201_6.3V6M  [C_0201]  256.47 38.64 90 top
CC395  0.1U_0402_25V6  [C_0402]  256.45 41.45 270 top
CC396  1U_0201_6.3V6M  [C_0201]  176.17 107.98 180 top
CC397  0.1U_0402_10V6K  [C_0402]  179.79 106.2 0 top
CC398  0.1U_0402_10V6K  [C_0402]  174.58 105.74 90 top
CC399  1U_0201_6.3V6M  [C_0201]  113.81 85.65 0 top
CC401  0.1U_0402_25V6  [C_0402]  119.59 90.78 270 top
CC402  1U_0201_6.3V6M  [C_0201]  111.21 87.34 90 top
CC405  10U_0402_6.3V6M  [C_0402]  164.98 94.28 90 top
CC406  1U_0201_6.3V6M  [C_0201]  120.48 107.72 90 bottom
CC407  1U_0201_6.3V6M  [C_0201]  110.57 87.34 90 top
CC408  1U_0201_6.3V6M  [C_0201]  253.8 36.94 270 top
CD1  0.1U_0402_10V6K  [C_0402]  170.01 52.86 180 top
CD2  2.2U_0201_6.3V6M  [C_0201]  170.01 51.46 180 top
CD3  10U_0402_6.3V6M  [C_0402]  173.44 50.95 0 top
CD4  10U_0402_6.3V6M  [C_0402]  173.44 49.93 0 top
CD5  1U_0201_6.3V6M  [C_0201]  171.53 50.82 90 top
CD6  1U_0201_6.3V6M  [C_0201]  172.42 48.79 270 top
CD7  10U_0402_6.3V6M  [C_0402]  172.93 40.66 0 top
CD8  10U_0402_6.3V6M  [C_0402]  172.93 41.55 0 top
CD9  1U_0201_6.3V6M  [C_0201]  171.15 40.66 180 top
CD10  -  [CK0402101V05_0402-2]  128.48 28.73 0 top
CD11  0.1U_0402_10V6K  [C_0402]  148.04 41.55 180 top
CD12  2.2U_0201_6.3V6M  [C_0201]  147.66 40.79 180 top
CD13  0.1U_0402_10V6K  [C_0402]  123.65 51.2 90 top
CD14  0.1U_0402_10V6K  [C_0402]  148.04 42.44 180 top
CD15  0.022U_0402_25V7K  [C_0402]  129.58 90.26 0 top
CD16  10U_0402_6.3V6M  [C_0402]  127.72 41.43 180 top
CD17  10U_0402_6.3V6M  [C_0402]  166.61 52.16 270 top
CD18  10U_0402_6.3V6M  [C_0402]  153.77 51.64 90 top
CD19  10U_0402_6.3V6M  [C_0402]  145.5 50.82 270 top
CD20  10U_0402_6.3V6M  [C_0402]  136.85 52.96 0 top
CD21  10U_0402_6.3V6M  [C_0402]  133.69 41.55 90 top
CD22  10U_0402_6.3V6M  [C_0402]  159.71 40.84 180 top
CD23  10U_0402_6.3V6M  [C_0402]  132.16 51.46 90 top
CD24  1U_0201_6.3V6M  [C_0201]  139.53 50.32 270 top
CD25  1U_0201_6.3V6M  [C_0201]  131.65 41.55 90 top
CD26  1U_0201_6.3V6M  [C_0201]  142.32 41.3 90 top
CD27  1U_0201_6.3V6M  [C_0201]  134.7 41.43 90 top
CD28  1U_0201_6.3V6M  [C_0201]  149.81 41.55 90 top
CD29  1U_0201_6.3V6M  [C_0201]  143.97 50.82 270 top
CD30  1U_0201_6.3V6M  [C_0201]  131.54 46.96 270 top
CD31  1U_0201_6.3V6M  [C_0201]  117.18 41.68 90 top
CD32  330U_2.5V_ESR17M_6.3X4.5  [C_6P3X4P5]  94.46 45.52 180 bottom
CD60  0.1U_0402_10V6K  [C_0402]  166.83 38.24 0 top
CD61  2.2U_0201_6.3V6M  [C_0201]  166.9 39.34 0 top
CD62  10U_0402_6.3V6M  [C_0402]  172.93 37.23 0 top
CD63  10U_0402_6.3V6M  [C_0402]  172.93 36.35 0 top
CD64  1U_0201_6.3V6M  [C_0201]  170.01 36.6 270 top
CD65  1U_0201_6.3V6M  [C_0201]  170.64 38.5 90 top
CD66  10U_0402_6.3V6M  [C_0402]  170.5 31.37 0 top
CD67  10U_0402_6.3V6M  [C_0402]  170.51 30.47 0 top
CD68  1U_0201_6.3V6M  [C_0201]  170.88 32.18 0 top
CD69  0.1U_0402_10V6K  [C_0402]  143.97 29.61 0 top
CD70  2.2U_0201_6.3V6M  [C_0201]  144.23 30.38 0 top
CD71  0.1U_0402_10V6K  [C_0402]  130 37.11 90 top
CD72  0.1U_0402_10V6K  [C_0402]  143.97 28.73 0 top
CD73  10U_0402_6.3V6M  [C_0402]  135.72 28.85 90 top
CD74  10U_0402_6.3V6M  [C_0402]  131.91 28.85 90 top
CD75  10U_0402_6.3V6M  [C_0402]  120.99 38 0 top
CD76  10U_0402_6.3V6M  [C_0402]  145.12 38.12 270 top
CD77  10U_0402_6.3V6M  [C_0402]  142.58 38.12 270 top
CD78  10U_0402_6.3V6M  [C_0402]  134.7 38.12 270 top
CD79  10U_0402_6.3V6M  [C_0402]  154.51 39.19 0 top
CD80  10U_0402_6.3V6M  [C_0402]  116.16 29.35 90 top
CD81  0.1U_0402_10V6K  [C_0402]  141.23 28.17 90 top
CD82  0.022U_0402_25V7K  [C_0402]  139.54 28.5 90 top
CD83  1U_0201_6.3V6M  [C_0201]  130.26 28.73 90 top
CD84  1U_0201_6.3V6M  [C_0201]  140.92 38.63 270 top
CD85  1U_0201_6.3V6M  [C_0201]  136.61 28.85 90 top
CD86  1U_0201_6.3V6M  [C_0201]  133.18 28.85 90 top
CD87  1U_0201_6.3V6M  [C_0201]  126.32 28.73 90 top
CD88  1U_0201_6.3V6M  [C_0201]  137.75 28.73 90 top
CD89  1U_0201_6.3V6M  [C_0201]  131.53 38.12 270 top
CD90  1U_0201_6.3V6M  [C_0201]  143.97 38.12 270 top
CD91  10P_0402_50V8J  [C_0402]  142.58 50.7 270 top
CD92  33P_0402_50V8J  [C_0402]  134.45 50.82 270 top
CD93  10P_0402_50V8J  [C_0402]  106.13 40.03 180 top
CD94  33P_0402_50V8J  [C_0402]  137.88 41.55 90 top
CD95  10P_0402_50V8J  [C_0402]  147.15 50.82 270 top
CD96  33P_0402_50V8J  [C_0402]  136.23 41.55 90 top
CD97  330U_D3_2.5VY_R6M  [C_D3]  137.24 56.28 180 top
CD98  1U_0201_6.3V6M  [C_0201]  172.55 50.82 90 top
CD99  1U_0201_6.3V6M  [C_0201]  171.79 48.79 270 top
CD100  1U_0201_6.3V6M  [C_0201]  170.64 36.6 270 top
CD101  1U_0201_6.3V6M  [C_0201]  171.28 38.5 90 top
CD102  2.2U_0201_6.3V6M  [C_0201]  170.01 52.09 180 top
CD103  2.2U_0201_6.3V6M  [C_0201]  166.9 39.98 0 top
CE1  10U_0402_6.3V6M  [C_0402]  277.17 45.62 0 bottom
CE2  0.1U_0201_10V6K  [C_0201]  277.58 44.8 0 bottom
CE3  10U_0402_6.3V6M  [C_0402]  28.15 46.28 270 bottom
CE4  0.1U_0201_10V6K  [C_0201]  29.85 45.88 270 bottom
CE5  0.01U_0402_50V7K  [C_0402]  274.87 44.16 270 top
CE6  0.01U_0402_50V7K  [C_0402]  46.06 40.12 0 bottom
CE7  10U_0402_6.3V6M  [C_0402]  277.17 46.51 0 bottom
CE8  10U_0402_6.3V6M  [C_0402]  29.11 45.92 270 bottom
CG1  12P_0402_50V8J  [C_0402]  221.32 67.33 0 bottom
CG2  12P_0402_50V8J  [C_0402]  223.23 68.62 270 bottom
CG3  0.1U_0201_10V6K  [C_0201]  200.82 81.61 90 top
CG4  22U_0603_6.3V6M  [C_0603]  193.45 77.85 0 top
CG5  0.1U_0201_10V6K  [C_0201]  199.72 82.18 180 top
CG6  0.1U_0201_10V6K  [C_0201]  199.72 81.57 180 top
CG7  0.1U_0201_10V6K  [C_0201]  214.6 87.74 270 top
CG9  0.1U_0201_10V6K  [C_0201]  207.5 97.7 0 top
CG10  0.1U_0201_10V6K  [C_0201]  211.33 97.74 90 top
CG11  22U_0603_6.3V6M  [C_0603]  188.68 93.5 0 bottom
CG12  0.1U_0201_10V6K  [C_0201]  214.6 89.14 90 top
CG13  1U_0201_6.3V6M  [C_0201]  201.4 81.58 0 top
CG14  1U_0201_6.3V6M  [C_0201]  199.6 92.35 0 top
CG15  1U_0201_6.3V6M  [C_0201]  196.29 84.3 270 top
CG16  4.7U_0402_6.3V6M  [C_0402]  196.42 82.07 90 top
CG17  4.7U_0402_6.3V6M  [C_0402]  199.47 87.09 0 top
CG18  1U_0201_6.3V6M  [C_0201]  214.18 85.57 0 top
CG19  1U_0201_6.3V6M  [C_0201]  217.43 91.66 0 top
CG20  1U_0201_6.3V6M  [C_0201]  211.16 96.29 270 top
CG21  1U_0201_6.3V6M  [C_0201]  213.32 83.18 180 top
CG22  1U_0201_6.3V6M  [C_0201]  213.67 90.03 180 top
CG23  1U_0201_6.3V6M  [C_0201]  213.09 84.64 180 top
CG24  10U_0402_6.3V6M  [C_0402]  209.21 96.42 270 top
CG25  1U_0201_6.3V6M  [C_0201]  194.47 96.34 270 top
CG26  10U_0402_6.3V6M  [C_0402]  213.9 88.42 180 top
CG27  10U_0402_6.3V6M  [C_0402]  195.42 94.62 0 top
CG28  10U_0402_6.3V6M  [C_0402]  198.65 97.16 0 top
CG29  4.7U_0402_6.3V6M  [C_0402]  199.09 96.27 0 top
CG30  10U_0402_6.3V6M  [C_0402]  199.57 89.29 0 top
CG31  22U_0603_6.3V6M  [C_0603]  188.8 97.18 90 bottom
CG32  4.7U_0402_6.3V6M  [C_0402]  199.56 88.29 0 top
CG33  1U_0201_6.3V6M  [C_0201]  199.6 93.11 0 top
CG34  22U_0603_6.3V6M  [C_0603]  198.18 93.55 180 top
CG36  22U_0603_6.3V6M  [C_0603]  233.13 90.09 180 bottom
CG37  10U_0402_6.3V6M  [C_0402]  201.34 96.38 270 top
CG38  10U_0402_6.3V6M  [C_0402]  202.36 96.38 270 top
CG39  22U_0603_6.3V6M  [C_0603]  204.39 96.64 270 top
CG40  22U_0603_6.3V6M  [C_0603]  206.04 96.64 270 top
CG41  22U_0603_6.3V6M  [C_0603]  207.26 96.93 270 top
CG42  4.7U_0402_6.3V6M  [C_0402]  200.53 83.02 180 top
CG43  0.1U_0201_10V6K  [C_0201]  199.67 86.22 0 top
CG46  0.01U_0402_16V7K  [C_0402]  183.14 80.27 270 bottom
CG49  0.1U_0201_10V6K  [C_0201]  211.76 80.89 270 top
CG50  4.7U_0402_6.3V6M  [C_0402]  213.61 80.93 0 top
CG51  1U_0201_6.3V6M  [C_0201]  212.34 80.89 270 top
CG52  0.1U_0201_10V6K  [C_0201]  196.84 97.51 90 top
CG53  0.1U_0201_10V6K  [C_0201]  198.24 84.52 270 top
CG54  1U_0201_6.3V6M  [C_0201]  196.27 97.5 90 top
CG55  4.7U_0402_6.3V6M  [C_0402]  199.56 85.43 0 top
CG56  1U_0201_6.3V6M  [C_0201]  226.43 123.99 90 bottom
CG57  1U_0201_6.3V6M  [C_0201]  185.29 130.21 270 top
CG58  1U_0201_6.3V6M  [C_0201]  211.6 123.65 270 bottom
CG59  1U_0201_6.3V6M  [C_0201]  226.4 121.69 270 bottom
CG60  1U_0201_6.3V6M  [C_0201]  226.39 125.89 90 bottom
CG61  1U_0201_6.3V6M  [C_0201]  188.45 120.42 0 top
CG62  1U_0201_6.3V6M  [C_0201]  185.28 123.6 270 top
CG63  1U_0201_6.3V6M  [C_0201]  185.3 131.58 270 top
CG64  1U_0201_6.3V6M  [C_0201]  187.6 128.03 180 top
CG65  1U_0201_6.3V6M  [C_0201]  184.89 130.07 270 bottom
CG66  1U_0201_6.3V6M  [C_0201]  199.73 125.19 270 bottom
CG67  1U_0201_6.3V6M  [C_0201]  211.54 129.31 270 bottom
CG68  1U_0201_6.3V6M  [C_0201]  211.62 125.39 270 bottom
CG69  1U_0201_6.3V6M  [C_0201]  184.89 131.85 270 bottom
CG70  22U_0603_6.3V6M  [C_0603]  211.28 121.82 270 bottom
CG71  22U_0603_6.3V6M  [C_0603]  210.43 116.2 270 bottom
CG72  22U_0603_6.3V6M  [C_0603]  200.04 131.73 270 bottom
CG73  10U_0402_6.3V6M  [C_0402]  211.66 126.26 270 top
CG74  10U_0402_6.3V6M  [C_0402]  226.61 133.45 90 bottom
CG75  10U_0402_6.3V6M  [C_0402]  211.4 118.6 90 bottom
CG76  10U_0402_6.3V6M  [C_0402]  214.2 129.18 270 top
CG77  1U_0201_6.3V6M  [C_0201]  193.4 133.25 90 top
CG78  1U_0201_6.3V6M  [C_0201]  199.8 128.85 270 bottom
CG79  1U_0201_6.3V6M  [C_0201]  184.89 125.88 270 bottom
CG80  10U_0402_6.3V6M  [C_0402]  200.52 124.35 270 bottom
CG81  10U_0402_6.3V6M  [C_0402]  185.2 125.46 270 top
CG82  10U_0402_6.3V6M  [C_0402]  185.27 133.37 90 top
CG83  10U_0402_6.3V6M  [C_0402]  199.5 130.45 90 top
CG84  10U_0402_6.3V6M  [C_0402]  223.86 117.76 270 bottom
CG85  10U_0402_6.3V6M  [C_0402]  226.53 119.44 90 bottom
CG86  10U_0402_6.3V6M  [C_0402]  199.5 122.2 270 top
CG87  10U_0402_6.3V6M  [C_0402]  199.5 125.75 270 top
CG88  820P_0402_50V7K  [C_0402]  184.76 127.79 90 bottom
CG89  820P_0402_50V7K  [C_0402]  226.52 127.79 90 bottom
CG90  1U_0201_6.3V6M  [C_0201]  244.67 82.34 0 top
CG91  1U_0201_6.3V6M  [C_0201]  243.56 105.51 180 bottom
CG92  1U_0201_6.3V6M  [C_0201]  236.08 66.24 180 bottom
CG93  1U_0201_6.3V6M  [C_0201]  244.54 66.89 0 bottom
CG94  1U_0201_6.3V6M  [C_0201]  247.22 99.08 0 top
CG95  1U_0201_6.3V6M  [C_0201]  236.17 90.57 180 bottom
CG96  1U_0201_6.3V6M  [C_0201]  245.7 99.08 0 top
CG97  1U_0201_6.3V6M  [C_0201]  244.43 99.08 180 top
CG98  1U_0201_6.3V6M  [C_0201]  246.97 97.05 0 top
CG99  1U_0201_6.3V6M  [C_0201]  239.33 66.85 180 bottom
CG100  1U_0201_6.3V6M  [C_0201]  247.1 73.3 0 top
CG101  1U_0201_6.3V6M  [C_0201]  234.27 79.4 90 top
CG102  1U_0201_6.3V6M  [C_0201]  236.08 66.84 180 bottom
CG103  1U_0201_6.3V6M  [C_0201]  243.48 81.67 180 bottom
CG104  1U_0201_6.3V6M  [C_0201]  247.35 90.57 0 bottom
CG105  1U_0201_6.3V6M  [C_0201]  245.7 90.57 180 bottom
CG106  1U_0201_6.3V6M  [C_0201]  243.67 90.57 180 bottom
CG107  1U_0201_6.3V6M  [C_0201]  246.15 66.89 0 bottom
CG108  10U_0402_6.3V6M  [C_0402]  237.96 90.93 180 top
CG109  10U_0402_6.3V6M  [C_0402]  247.47 91.02 270 top
CG110  10U_0402_6.3V6M  [C_0402]  236.23 81.82 180 bottom
CG111  1U_0201_6.3V6M  [C_0201]  239.73 79.65 180 top
CG112  1U_0201_6.3V6M  [C_0201]  247.92 75.33 0 top
CG113  1U_0201_6.3V6M  [C_0201]  237.57 81.43 180 top
CG114  10U_0402_6.3V6M  [C_0402]  247.46 67.17 0 top
CG115  10U_0402_6.3V6M  [C_0402]  244.44 81.55 0 top
CG116  10U_0402_6.3V6M  [C_0402]  239.6 81.56 180 top
CG117  10U_0402_6.3V6M  [C_0402]  241.73 66.99 0 top
CG118  10U_0402_6.3V6M  [C_0402]  244.36 90.96 270 top
CG119  10U_0402_6.3V6M  [C_0402]  245.93 105.65 180 bottom
CG120  10U_0402_6.3V6M  [C_0402]  245.54 81.83 0 bottom
CG121  10U_0402_6.3V6M  [C_0402]  239.56 81.89 0 bottom
CG122  820P_0402_50V7K  [C_0402]  241.32 105.54 0 bottom
CG123  820P_0402_50V7K  [C_0402]  242.27 66.7 0 bottom
CG124  0.1U_0201_10V6K  [C_0201]  214.21 95.69 225 top
CG126  1U_0201_6.3V6M  [C_0201]  214.2 84.86 0 top
CG127  1U_0201_6.3V6M  [C_0201]  214.2 84.1 0 top
CG128  1U_0201_6.3V6M  [C_0201]  214.69 92.21 0 top
CG129  1U_0201_6.3V6M  [C_0201]  214.69 91.65 0 top
CG130  1U_0201_6.3V6M  [C_0201]  213.71 87.65 180 top
CG131  1U_0201_6.3V6M  [C_0201]  213.67 90.62 180 top
CG132  10U_0402_6.3V6M  [C_0402]  208.31 96.42 270 top
CG133  10U_0402_6.3V6M  [C_0402]  203.31 96.45 270 top
CG134  1U_0201_6.3V6M  [C_0201]  199.59 90.94 0 top
CG135  0.1U_0201_10V6K  [C_0201]  211.94 82.11 90 top
CG136  1U_0201_6.3V6M  [C_0201]  198.08 85.5 180 top
CG137  1U_0201_6.3V6M  [C_0201]  210.39 81.38 270 top
CG138  22U_0603_6.3V6M  [C_0603]  200.03 122.46 270 bottom
CG139  22U_0603_6.3V6M  [C_0603]  201.26 131.74 270 bottom
CG140  1U_0201_6.3V6M  [C_0201]  213.95 120.06 180 top
CG141  1U_0201_6.3V6M  [C_0201]  211.92 123.72 90 top
CG142  1U_0201_6.3V6M  [C_0201]  246.01 67.22 0 top
CG143  22U_0603_6.3V6M  [C_0603]  193.64 115.34 270 bottom
CG144  22U_0603_6.3V6M  [C_0603]  194.94 115.37 270 bottom
CG145  22U_0603_6.3V6M  [C_0603]  184.61 133.36 90 bottom
CG146  22U_0603_6.3V6M  [C_0603]  184.62 121.29 90 bottom
CG147  22U_0603_6.3V6M  [C_0603]  211.26 133.26 90 bottom
CG148  22U_0603_6.3V6M  [C_0603]  243.71 66.97 0 top
CG149  22U_0603_6.3V6M  [C_0603]  247.56 66.55 0 bottom
CG150  22U_0603_6.3V6M  [C_0603]  247.64 82.04 0 bottom
CG151  22U_0603_6.3V6M  [C_0603]  236.19 81.52 180 top
CG152  22U_0603_6.3V6M  [C_0603]  244.87 98.11 180 top
CG153  22U_0603_6.3V6M  [C_0603]  236.09 90.84 180 top
CG154  22U_0603_6.3V6M  [C_0603]  247.8 105.67 90 bottom
CG155  22U_0603_6.3V6M  [C_0603]  249.75 101.77 270 top
CG156  22U_0603_6.3V6M  [C_0603]  244.7 74.39 180 top
CG157  22U_0603_6.3V6M  [C_0603]  245.88 91 270 top
CG158  1U_0201_6.3V6M  [C_0201]  211.96 133.47 90 top
CG159  1U_0201_6.3V6M  [C_0201]  237.93 82.22 0 bottom
CG160  1U_0201_6.3V6M  [C_0201]  211.6 131.85 270 bottom
CG161  1U_0201_6.3V6M  [C_0201]  211.92 131.96 270 top
CG162  1U_0201_6.3V6M  [C_0201]  211.96 122.2 270 top
CG163  1U_0201_6.3V6M  [C_0201]  226.41 130.09 270 bottom
CG164  1U_0201_6.3V6M  [C_0201]  226.45 131.72 270 bottom
CG165  1U_0201_6.3V6M  [C_0201]  226.37 122.49 90 bottom
CG166  1U_0201_6.3V6M  [C_0201]  191.37 130.33 270 top
CG167  1U_0201_6.3V6M  [C_0201]  226.46 135.09 90 bottom
CG168  1U_0201_6.3V6M  [C_0201]  199.75 126.13 90 bottom
CG169  1U_0201_6.3V6M  [C_0201]  199.41 123.65 270 top
CG170  1U_0201_6.3V6M  [C_0201]  193.4 130.33 270 top
CG171  1U_0201_6.3V6M  [C_0201]  191.37 133.25 90 top
CG172  1U_0201_6.3V6M  [C_0201]  216.14 115.72 270 bottom
CG173  1U_0201_6.3V6M  [C_0201]  200.39 128.85 270 bottom
CG174  10U_0402_6.3V6M  [C_0402]  246.97 97.94 0 top
CG175  1U_0201_6.3V6M  [C_0201]  237.73 66.84 180 bottom
CG176  1U_0201_6.3V6M  [C_0201]  244.12 81.67 0 bottom
CG177  1U_0201_6.3V6M  [C_0201]  244.56 75.33 180 top
CG178  1U_0201_6.3V6M  [C_0201]  244.04 73.44 180 top
CG179  1U_0201_6.3V6M  [C_0201]  240.92 66.86 0 bottom
CG180  1U_0201_6.3V6M  [C_0201]  247.88 81.29 0 top
CG181  1U_0201_6.3V6M  [C_0201]  234.41 102.04 270 top
CG182  1U_0201_6.3V6M  [C_0201]  239.71 91.13 180 top
CG183  1U_0201_6.3V6M  [C_0201]  238.26 105.49 90 bottom
CG184  1U_0201_6.3V6M  [C_0201]  236.22 105.54 90 bottom
CG185  1U_0201_6.3V6M  [C_0201]  237.94 81.64 0 bottom
CG186  1U_0201_6.3V6M  [C_0201]  237.95 90.57 0 bottom
CG187  1U_0201_6.3V6M  [C_0201]  244.43 97.05 180 top
CG188  1U_0201_6.3V6M  [C_0201]  240.24 90.57 0 bottom
CG189  1U_0201_6.3V6M  [C_0201]  233.2 94.7 270 bottom
CG190  0.01U_0402_16V7K  [C_0402]  220.92 114.82 90 bottom
CG191  0.01U_0402_16V7K  [C_0402]  187.83 116.01 45 bottom
CG192  0.01U_0402_16V7K  [C_0402]  231.08 100.65 90 bottom
CG193  0.01U_0402_16V7K  [C_0402]  231.2 71.05 180 bottom
CG194  0.1U_0201_10V6K  [C_0201]  213.03 95.83 270 top
CG195  0.1U_0201_10V6K  [C_0201]  214.27 96.73 45 top
CG196  0.22U_0402_16V7K  [C_0402]  238.14 45.07 0 bottom
CG197  0.1U_0201_10V6K  [C_0201]  234.94 40.66 0 bottom
CG200  0.1U_0201_10V6K  [C_0201]  236.81 61.12 0 bottom
CG202  22U_0603_6.3V6M  [C_0603]  214.41 94.44 0 top
CG203  4.7U_0402_6.3V6M  [C_0402]  198.09 94.62 180 top
CG204  4.7U_0402_6.3V6M  [C_0402]  199.11 95.16 0 top
CG205  4.7U_0402_6.3V6M  [C_0402]  199.52 94.14 0 top
CG206  0.1U_0201_10V6K  [C_0201]  200.56 80.45 270 top
CG207  0.1U_0201_10V6K  [C_0201]  198.19 79.68 0 top
CG208  0.1U_0201_10V6K  [C_0201]  197.7 79.05 180 top
CG209  0.1U_0201_10V6K  [C_0201]  199.6 91.72 0 top
CG210  0.1U_0201_10V6K  [C_0201]  198.46 82.45 90 top
CG211  0.1U_0201_10V6K  [C_0201]  201.18 80.47 0 top
CG212  1U_0201_6.3V6M  [C_0201]  197.82 82.45 90 top
CG213  1U_0201_6.3V6M  [C_0201]  197.19 82.45 90 top
CG214  1U_0201_6.3V6M  [C_0201]  199.75 90.21 0 top
CG215  0.1U_0201_10V6K  [C_0201]  197.79 80.52 180 top
CG216  0.1U_0201_10V6K  [C_0201]  199.39 80.43 270 top
CG217  10U_0402_6.3V6M  [C_0402]  213.15 83.91 180 top
CG218  10U_0402_6.3V6M  [C_0402]  212.17 95.56 225 top
CG219  22U_0603_6.3V6M  [C_0603]  212.26 94 270 top
CG220  22U_0603_6.3V6M  [C_0603]  213.46 93.35 270 top
CG221  22U_0603_6.3V6M  [C_0603]  213.49 86.45 180 top
CG222  22U_0603_6.3V6M  [C_0603]  210.26 96.39 270 top
CG223  22U_0603_6.3V6M  [C_0603]  230.23 94.82 270 bottom
CG269  0.1U_0201_10V6K  [C_0201]  245.11 39.87 270 bottom
CG334  10U_0402_6.3V6M  [C_0402]  246.33 43.71 270 bottom
CG335  100P_0402_50V8J  [C_0402]  244.48 44.84 90 bottom
CG336  100P_0402_50V8J  [C_0402]  243.6 45.04 180 bottom
CG337  0.1U_0201_10V6K  [C_0201]  244.55 39.88 270 bottom
CG338  10U_0402_6.3V6M  [C_0402]  241.76 43.71 270 bottom
CG339  22U_0603_6.3V6M  [C_0603]  241.61 39.41 180 bottom
CG340  0.1U_0201_10V6K  [C_0201]  237.19 64.79 0 bottom
CG531  0.22U_0402_16V7K  [C_0402]  178.14 85.7 0 top
CG532  0.22U_0402_16V7K  [C_0402]  178.14 84.81 0 top
CG533  0.22U_0402_16V7K  [C_0402]  175.34 86.76 0 top
CG534  0.22U_0402_16V7K  [C_0402]  175.34 85.88 0 top
CG535  0.22U_0402_16V7K  [C_0402]  178.14 86.97 0 top
CG536  0.22U_0402_16V7K  [C_0402]  178.14 87.86 0 top
CG537  0.22U_0402_16V7K  [C_0402]  175.34 88.92 0 top
CG538  0.22U_0402_16V7K  [C_0402]  175.34 88.03 0 top
CG539  0.22U_0402_16V7K  [C_0402]  178.14 89.13 0 top
CG540  0.22U_0402_16V7K  [C_0402]  178.14 90.02 0 top
CG541  0.22U_0402_16V7K  [C_0402]  175.34 91.08 0 top
CG542  0.22U_0402_16V7K  [C_0402]  175.34 90.19 0 top
CG543  0.22U_0402_16V7K  [C_0402]  178.14 91.29 0 top
CG544  0.22U_0402_16V7K  [C_0402]  178.14 92.17 0 top
CG545  0.22U_0402_16V7K  [C_0402]  175.34 93.24 0 top
CG546  0.22U_0402_16V7K  [C_0402]  175.34 92.35 0 top
CG563  0.1U_0201_10V6K  [C_0201]  240.9 62.51 90 bottom
CG564  1U_0201_6.3V6M  [C_0201]  196.4 96.44 270 top
CG565  1U_0201_6.3V6M  [C_0201]  193.91 97.52 90 top
CG566  1U_0201_6.3V6M  [C_0201]  210.58 82.58 0 top
CG567  1U_0201_6.3V6M  [C_0201]  195.1 81.66 270 top
CG568  1U_0201_6.3V6M  [C_0201]  212.91 80.89 270 top
CG569  1U_0201_6.3V6M  [C_0201]  190.2 97.56 90 bottom
CG570  10U_0402_6.3V6M  [C_0402]  190.07 95.91 270 bottom
CG571  10U_0402_6.3V6M  [C_0402]  195.53 97.86 180 top
CG572  10U_0402_6.3V6M  [C_0402]  247.35 43.71 270 bottom
CG573  10U_0402_6.3V6M  [C_0402]  240.75 43.71 270 bottom
CG574  10U_0402_6.3V6M  [C_0402]  241.76 40.92 90 bottom
CG575  0.1U_0402_10V6K  [C_0402]  246.33 41.04 90 bottom
CG576  4.7U_0402_6.3V6M  [C_0402]  240.75 40.92 90 bottom
CG2818  0.1U_0201_10V6K  [C_0201]  234.95 55.66 180 bottom
CH1  0.1U_0402_10V6K  [C_0402]  219.28 8.66 90 top
CH2  0.1U_0402_10V6K  [C_0402]  182.33 53.36 180 bottom
CH3  10P_0402_50V8J  [C_0402]  182.33 49.31 180 bottom
CH4  22P_0402_50V8J  [C_0402]  218.19 34.97 180 bottom
CH5  22P_0402_50V8J  [C_0402]  218.19 32.42 180 bottom
CH6  10P_0402_50V8D  [C_0402]  186.64 20.34 90 bottom
CH7  10P_0402_50V8D  [C_0402]  186.64 19.45 270 bottom
CH9  1U_0201_6.3V6M  [C_0201]  191.34 18.31 90 top
CH10  1U_0201_6.3V6M  [C_0201]  190.34 20.35 270 top
CH11  -  [CK0402101V05_0402-2]  187 15.53 90 bottom
CH12  22U_0603_6.3V6K  [C_0603]  201.72 36.45 0 top
CH13  1U_0201_6.3V6M  [C_0201]  201.85 35.33 0 top
CH14  0.1U_0402_10V6K  [C_0402]  204.04 32.66 90 top
CH15  0.1U_0402_10V6K  [C_0402]  191.6 35.2 270 top
CH16  1U_0201_6.3V6M  [C_0201]  191.47 14.5 0 bottom
CH17  1P_0402_50V8  [C_0402]  217.61 39.6 270 bottom
CH18  22U_0603_6.3V6K  [C_0603]  187.03 36.98 0 bottom
CH19  1U_0201_6.3V6M  [C_0201]  187.66 39.39 90 bottom
CH20  22U_0402_6.3V6M  [C_0402]  219.09 36.93 90 bottom
CH21  1U_0201_6.3V6M  [C_0201]  217.42 40.89 270 bottom
CH22  0.1U_0402_10V6K  [C_0402]  205.95 32.28 0 top
CH23  1U_0201_6.3V6M  [C_0201]  213.82 43.58 0 bottom
CH24  1P_0402_50V8  [C_0402]  217.05 43.63 180 bottom
CH25  0.1U_0402_10V6K  [C_0402]  190.58 14.5 180 bottom
CH26  1U_0201_6.3V6M  [C_0201]  189.57 19.2 90 top
CH27  0.1U_0402_10V6K  [C_0402]  179.66 14.93 180 top
CH29  1U_0201_6.3V6M  [C_0201]  208.49 19.94 180 top
CH30  0.1U_0402_10V6K  [C_0402]  210.9 17.42 0 top
CH31  1U_0201_6.3V6M  [C_0201]  211.16 18.82 0 top
CH32  0.1U_0402_10V6K  [C_0402]  191.6 32.41 90 top
CH33  0.1U_0402_10V6K  [C_0402]  197.44 27.07 0 top
CH34  0.1U_0402_10V6K  [C_0402]  188.8 14.5 180 bottom
CH35  4.7U_0402_6.3V6M  [C_0402]  207.35 22.5 180 top
CH36  4.7U_0402_6.3V6M  [C_0402]  212.68 16.53 90 top
CH60  0.1U_0402_10V6K  [C_0402]  191.22 44.5 270 bottom
CH61  0.1U_0402_10V6K  [C_0402]  190.28 44.5 270 bottom
CH62  1U_0201_6.3V6M  [C_0201]  201.41 28.74 270 top
CH63  1P_0402_50V8  [C_0402]  208.23 24.2 270 top
CH64  1P_0402_50V8  [C_0402]  206.52 19.89 90 top
CH65  10P_0402_50V8J  [C_0402]  184.79 24.1 0 bottom
CH66  2.2P_0402_50V8C  [C_0402]  218.72 14.5 180 bottom
CH67  2.2P_0402_50V8C  [C_0402]  219.59 13.1 0 bottom
CH68  2.2P_0402_50V8C  [C_0402]  218.72 13.1 180 bottom
CH69  2.2P_0402_50V8C  [C_0402]  218.99 15.93 180 bottom
CH70  10P_0402_50V8J  [C_0402]  195.28 18.51 180 top
CH71  100P_0402_50V8J  [C_0402]  215.6 24.53 270 top
CH72  100P_0402_50V8J  [C_0402]  218.27 24.03 180 top
CH73  100P_0402_50V8J  [C_0402]  193.38 18.44 270 top
CH75  0.1U_0402_10V6K  [C_0402]  194.04 44.52 270 bottom
CH76  0.1U_0402_10V6K  [C_0402]  194.97 44.52 270 bottom
CH77  0.1U_0402_10V6K  [C_0402]  192.19 44.51 270 bottom
CH78  0.1U_0402_10V6K  [C_0402]  193.13 44.51 270 bottom
CH79  100P_0402_50V8J  [C_0402]  215.19 9.55 270 top
CH80  0.1U_0402_10V6K  [C_0402]  122.92 109.5 180 bottom
CH81  0.1U_0402_10V6K  [C_0402]  210.69 28.86 90 top
CH82  1U_0201_6.3V6M  [C_0201]  192.61 18.95 180 top
CH83  1U_0201_6.3V6M  [C_0201]  190.97 20.35 270 top
CH84  1U_0201_6.3V6M  [C_0201]  188.93 19.2 90 top
CH85  1U_0201_6.3V6M  [C_0201]  211.16 18.18 0 top
CH86  1U_0201_6.3V6M  [C_0201]  208.49 20.5 180 top
CH101  22U_0402_6.3V6M  [C_0402]  218.2 36.93 90 bottom
CH102  22U_0402_6.3V6M  [C_0402]  165.56 100.28 270 top
CH103  22U_0402_6.3V6M  [C_0402]  162.72 102.08 0 top
CH104  22U_0402_6.3V6M  [C_0402]  186.9 39.27 90 bottom
CH105  22U_0402_6.3V6M  [C_0402]  218.14 41.35 270 bottom
CH106  22U_0402_6.3V6M  [C_0402]  215.22 44.55 270 bottom
CH107  27P_0402_50V8J  [C_0402]  63.1 21.56 0 bottom
CH108  0.1U_0402_16V7K  [C_0402]  190 15.95 180 top
CH109  22U_0402_6.3V6M  [C_0402]  220.05 36.94 90 bottom
CK1  0.1U_0201_10V6K  [C_0201]  149.7 6.35 270 top
CK2  0.1U_0201_10V6K  [C_0201]  139.86 6.34 270 top
CK3  0.1U_0201_10V6K  [C_0201]  150.83 25.66 180 top
CK4  0.1U_0402_25V6  [C_0402]  141.84 6.55 270 top
CK5  0.1U_0402_16V7K  [C_0402]  153.83 12.85 0 top
CK8  4.7U_0402_6.3V6M  [C_0402]  133.1 10.75 180 top
